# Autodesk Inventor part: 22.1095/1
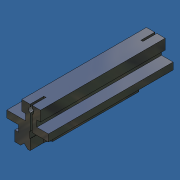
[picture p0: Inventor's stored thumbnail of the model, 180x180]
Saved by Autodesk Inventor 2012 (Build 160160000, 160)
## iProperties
Created: 2007-06
Part Number: 22.1095/1
Material: UHMW, Black
Document SubType Name: Modeling
Designer: Andy Moles
Density: 0.94 g/cm^3
Description: MACHINE TO 22.1095/1
Stock Number: 22.1087 DOUBLE SLIDE BAR
Mass: 34.3979 g
Surface Area: 140.629 cm^2
Volume: 36.5935 cm^3
Vendor: F
Author: Andy Moles
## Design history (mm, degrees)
sketch "Sketch1"
  geometry: L1 (4.1, 0)-(4.1, -4.6) reference; L2 (17.5, 0)-(4.1, 0) reference; L3 (17.5, 5)-(17.5, 0) reference; L4 (9.1, 5)-(17.5, 5) reference; L5 (9.1, 9.6)-(9.1, 5) reference; L6 (11.75, 9.6)-(9.1, 9.6) reference; L7 (11.75, 17)-(11.75, 9.6) reference; L8 (-1.75, 17)-(11.75, 17) reference; L9 (-1.75, 9.6)-(-1.75, 17) reference; L10 (0.9, 9.6)-(-1.75, 9.6) reference; L11 (0.9, 5)-(0.9, 9.6) reference; L12 (-12.5, 5)-(0.9, 5) reference; L13 (-12.5, 0)-(-12.5, 5) reference; L14 (-4.1, 0)-(-12.5, 0) reference; L15 (-4.1, -4.6)-(-4.1, 0) reference; L16 (-6.75, -4.6)-(-4.1, -4.6) reference; L17 (-6.75, -12)-(-6.75, -4.6) reference; L18 (6.75, -4.6)-(6.75, -12) reference; L19 (4.1, -4.6)-(6.75, -4.6) reference; L20 (-2.5, -12)-(0, -9.5); L21 (0, -9.5)-(2.5, -12); L22 (6.75, -12)-(2.5, -12); L23 (-2.5, -12)-(-6.75, -12); 4 further points
  constraints: 46 end point, 11 horizontal, 10 vertical, 1 midpoint, 1 perpendicular, 1 vertical alignment, 21 other
  dimensions: "d1" = 90 deg angle of L21 L20
extrude "Extrusion1" new body sketch "Sketch1" stored distance "d2" = 90; taper "d3" = 0 deg
sketch "Sketch2"
  geometry: L1 (4.25, 0)-(0, 0) reference; L2 (4.25, -90)-(4.25, 0) reference; L3 (1.75, -9.67)-(1.75, 0); L4 (-9.25, -90)-(-9.25, 0) reference; A1 r 5 centre (6.75, -9.67) between (1.75, -9.67) and (4.25, -14); 1 further point
  constraints: 2 end point, 2 point on circle, 2 point on line, 1 centre point, 1 parallel, 1 tangent
  dimensions: "d4" = 10 diameter of A1; "d5" = 11 distance between parallel lines of L3 L4; "d6" = 14 distance from line of A1.end L1
extrude "Extrusion2" cut sketch "Sketch2" distance "d7" = 12; taper "d8" = 0 deg
sketch "Sketch3"
  geometry: L1 (-1.75, 17)-(11.75, 17) reference; L2 (-1.75, 9.6)-(-1.75, 17) reference; L3 (4.25, -12)-(2.5, -12) reference; L4 (4.25, -3.157)-(5.75, -3.157); L5 (4.25, 17)-(4.25, 15.154); L6 (4.25, 11.446)-(4.25, -3.157); L7 (5.75, -3.157)-(5.75, 11.446); L8 (5.75, 15.154)-(5.75, 17); L9 (4.25, 17)-(5.75, 17); A1 r 2 centre (5, 13.3) between (4.25, 15.154) and (4.25, 11.446); A2 r 2 centre (5, 13.3) between (5.75, 11.446) and (5.75, 15.154); 6 further points
  constraints: 12 end point, 5 midpoint, 4 parallel, 4 perpendicular, 4 point on circle, 3 vertical alignment, 2 centre point, 2 point on line, 1 collinear, 1 horizontal alignment
  dimensions: "d9" = 1.5 distance of L4.start L4.end
extrude "Extrusion3" cut sketch "Sketch3" distance "d11" = 10; taper "d12" = 0 deg
mirror "Mirror1"
thread "Thread1" dims "d13" = 10, "d14" = 0
thread "Thread2" dims "d15" = 10, "d16" = 0
thread "Thread3" dims "d17" = 10, "d18" = 0
thread "Thread4" dims "d19" = 10, "d20" = 0
body "Solid1"
other parameters: "d0" = 2.5, "d10" = 4
